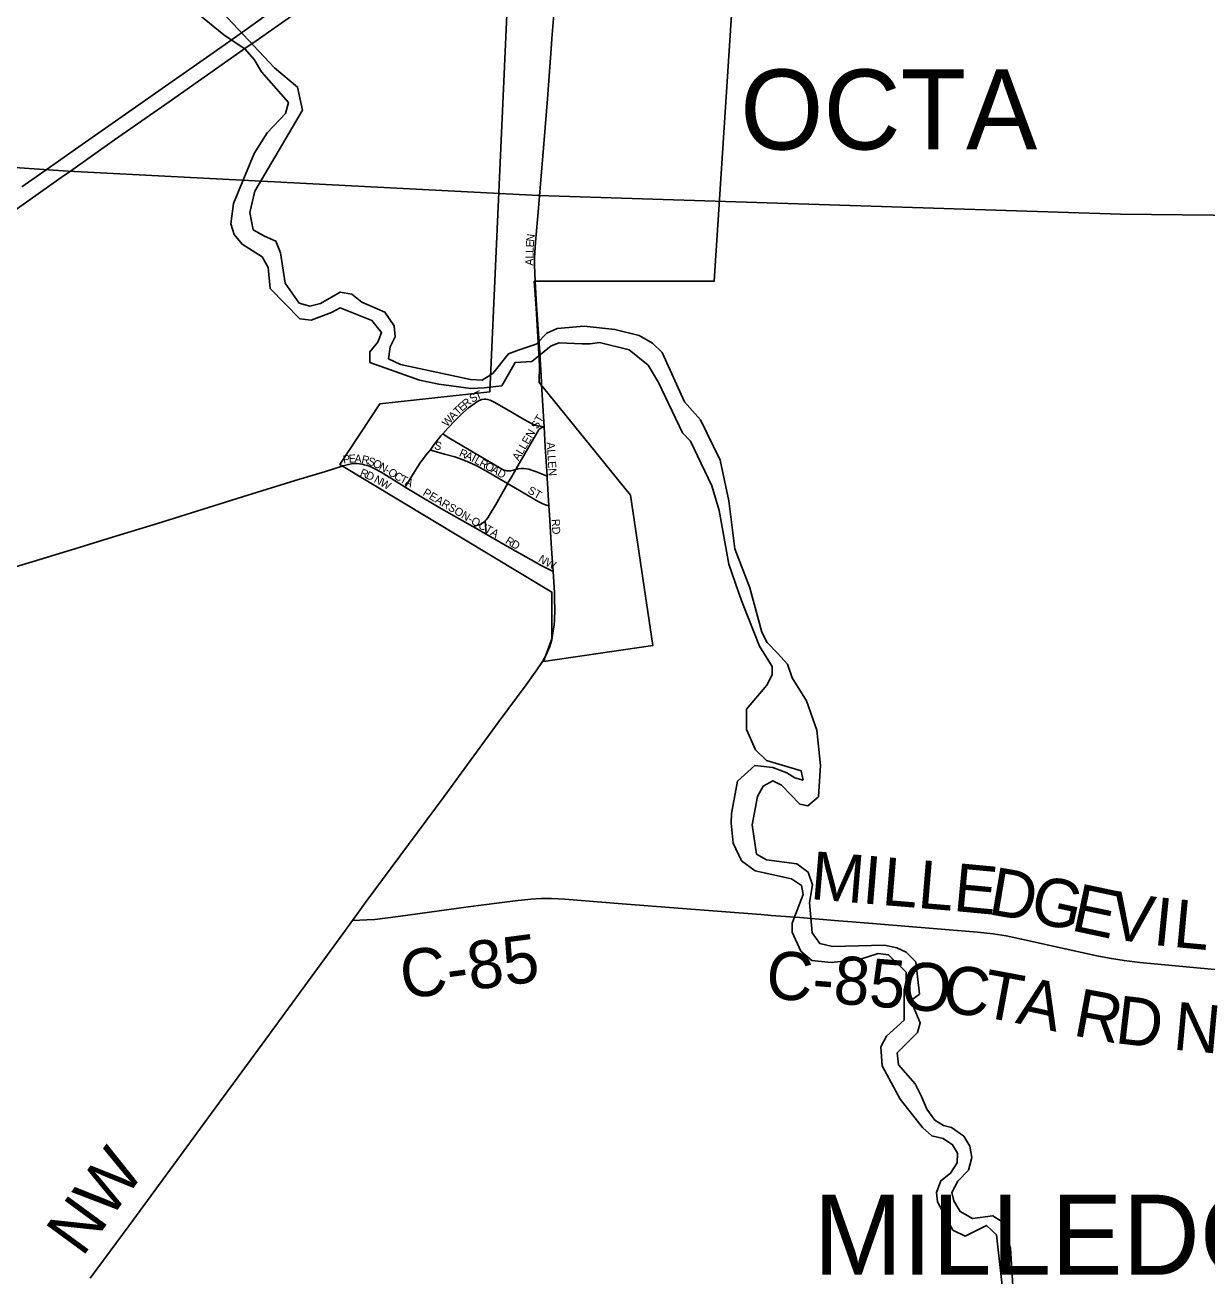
# Model space of a CAD drawing. Extents: x -49 to -8.2, y 9.4 to 23.5.
# Drawn here: x -41.383 to -40.683, y 16.498 to 17.238 of the extents above; entities that cross this region are included whole.
import ezdxf

# ---------------------------------------------------------------- set-up
doc = ezdxf.new("R2010")
doc.units = 0
for name, color, linetype in [('GM_X_City_Street', 7, 'Continuous'), ('GM_X_City_Street_Text', 7, 'Continuous'), ('GM_X_Corporation', 7, 'Continuous'), ('GM_X_Corporation_Text', 7, 'Continuous'), ('GM_X_County_Road', 7, 'Continuous'), ('GM_X_County_Road_Text', 7, 'Continuous'), ('GM_X_Interstate_Route', 7, 'Continuous'), ('GM_X_Major_River', 7, 'Continuous'), ('GM_X_Township', 7, 'Continuous')]:
    doc.layers.add(name, color=color, linetype=linetype)

msp = doc.modelspace()

# ---------------------------------------------------------------- linework, layer by layer
at = {"layer": 'GM_X_City_Street'}
for points in [[(-41.07819, 17.13694), (-41.07627, 17.16039), (-41.07346, 17.19439), (-41.07111, 17.22662), (-41.07087, 17.22997), (-41.06839, 17.26088)], [(-41.08079, 17.08632), (-41.08118, 17.09559), (-41.08113, 17.10021), (-41.08053, 17.10948), (-41.0788, 17.12956), (-41.07819, 17.13694)], [(-41.07555, 17.0002), (-41.07707, 17.02518)], [(-41.13552, 16.996), (-41.13246, 16.99939), (-41.12818, 17.00386), (-41.12367, 17.00837), (-41.12026, 17.01136), (-41.11782, 17.01327), (-41.11527, 17.01499), (-41.11392, 17.01574), (-41.11247, 17.01629), (-41.11094, 17.01655)], [(-41.11094, 17.01655), (-41.11003, 17.0166), (-41.10895, 17.01641), (-41.1075, 17.01594), (-41.10475, 17.01465), (-41.09681, 17.0101), (-41.08625, 17.0039), (-41.08221, 17.00177), (-41.08081, 17.00117), (-41.07935, 17.00073), (-41.07783, 17.00052), (-41.07555, 17.0002)], [(-41.09222, 16.97497), (-41.09021, 16.97839), (-41.07901, 16.99785), (-41.07858, 16.9986), (-41.07815, 16.99908), (-41.07736, 16.99959), (-41.07555, 17.0002)], [(-41.0737, 16.97089), (-41.07484, 16.98843), (-41.07555, 17.0002)], [(-41.14285, 16.98665), (-41.14078, 16.98951), (-41.1366, 16.99478), (-41.13552, 16.996)], [(-41.13552, 16.996), (-41.13538, 16.99591), (-41.13202, 16.99366), (-41.11322, 16.98258), (-41.10116, 16.97544), (-41.09975, 16.97476), (-41.09827, 16.97429), (-41.09756, 16.97413), (-41.09673, 16.97411), (-41.09597, 16.97417), (-41.09518, 16.97422), (-41.09366, 16.97457), (-41.09222, 16.97497)], [(-41.15781, 16.96456), (-41.15738, 16.96524), (-41.15374, 16.971), (-41.15075, 16.97611), (-41.14854, 16.97941), (-41.14699, 16.98147), (-41.14558, 16.98345), (-41.14285, 16.98665)], [(-41.14285, 16.98665), (-41.14205, 16.98623), (-41.13447, 16.9841), (-41.12844, 16.9824), (-41.12399, 16.98091), (-41.11965, 16.97916), (-41.11541, 16.97712), (-41.10855, 16.97336), (-41.10191, 16.96943), (-41.09714, 16.96666)], [(-41.19446, 16.97705), (-41.19131, 16.97787), (-41.18955, 16.97822), (-41.18793, 16.97842), (-41.18625, 16.9785), (-41.18475, 16.9783), (-41.18329, 16.97806), (-41.182, 16.97779), (-41.18033, 16.97734), (-41.17889, 16.97684), (-41.1761, 16.97561), (-41.17207, 16.97336), (-41.16153, 16.96681), (-41.15781, 16.96456)], [(-41.09222, 16.97497), (-41.09066, 16.97542), (-41.08912, 16.97558), (-41.08757, 16.97553), (-41.08602, 16.97535), (-41.08449, 16.97504), (-41.08299, 16.97463), (-41.08004, 16.97362), (-41.07717, 16.97239), (-41.0737, 16.97089)], [(-41.09714, 16.96666), (-41.09469, 16.97081), (-41.09222, 16.97497)], [(-41.07269, 16.95334), (-41.07363, 16.96986), (-41.0737, 16.97089)], [(-41.15781, 16.96456), (-41.14691, 16.95797), (-41.1362, 16.95169), (-41.11775, 16.94117)], [(-41.11038, 16.94454), (-41.10982, 16.94513), (-41.10888, 16.94634), (-41.10803, 16.94762), (-41.10414, 16.95431), (-41.09729, 16.96643), (-41.09714, 16.96666)], [(-41.09714, 16.96666), (-41.0925, 16.96395), (-41.07906, 16.95595), (-41.07627, 16.95456), (-41.07479, 16.95406), (-41.07269, 16.95334)], [(-41.07023, 16.9146), (-41.0711, 16.92807), (-41.07239, 16.94819), (-41.07269, 16.95334)], [(-41.11775, 16.94117), (-41.11737, 16.94127), (-41.11559, 16.9417), (-41.11347, 16.94235), (-41.11281, 16.94264), (-41.11211, 16.94309), (-41.11088, 16.94402), (-41.11038, 16.94454)], [(-41.11775, 16.94117), (-41.11597, 16.94015), (-41.10988, 16.93663)], [(-41.10988, 16.93663), (-41.10992, 16.93734), (-41.11005, 16.93929), (-41.11022, 16.94191), (-41.11036, 16.94419), (-41.11038, 16.94454)], [(-41.10988, 16.93663), (-41.09581, 16.9285), (-41.07683, 16.91787), (-41.07403, 16.91648), (-41.07023, 16.9146)], [(-41.06942, 16.90207), (-41.07023, 16.9146)]]:
    msp.add_lwpolyline(points, dxfattribs=at)
at = {"layer": 'GM_X_Corporation'}
msp.add_lwpolyline([(-40.96096, 17.29862), (-40.97477, 17.0863), (-41.08141, 17.08629), (-41.08018, 17.07045), (-41.07818, 17.03646), (-41.07853, 17.02636), (-41.02443, 16.9598), (-41.01126, 16.87068), (-41.07582, 16.86121), (-41.07096, 16.87465), (-41.071, 16.90237), (-41.19642, 16.97793), (-41.1728, 17.01378), (-41.10769, 17.02084), (-41.09569, 17.28796)], dxfattribs=at)
at = {"layer": 'GM_X_County_Road'}
for points in [[(-41.07707, 17.02518), (-41.07714, 17.02675), (-41.07813, 17.04401), (-41.07996, 17.07222), (-41.08079, 17.08632)], [(-41.52576, 16.81187), (-41.52231, 16.81517), (-41.50199, 16.83436), (-41.43997, 16.89308), (-41.43421, 16.89825), (-41.43062, 16.90117), (-41.42685, 16.90383), (-41.42421, 16.9054), (-41.42146, 16.90677), (-41.41718, 16.90852), (-41.40984, 16.91096), (-41.3786, 16.92032), (-41.35336, 16.92803), (-41.33107, 16.93481), (-41.30437, 16.94307), (-41.25398, 16.95879), (-41.22281, 16.96835), (-41.20499, 16.97382), (-41.19446, 16.97705)], [(-41.07655, 16.86137), (-41.07458, 16.86481), (-41.07222, 16.8702), (-41.071, 16.87416), (-41.07029, 16.87818), (-41.0696, 16.88278), (-41.06936, 16.88587), (-41.06921, 16.89204), (-41.06935, 16.8982), (-41.06942, 16.90207)], [(-41.18891, 16.70801), (-41.18081, 16.71931), (-41.16598, 16.73913), (-41.13472, 16.78145), (-41.12471, 16.79521), (-41.10269, 16.82511), (-41.08619, 16.84755), (-41.07992, 16.85641), (-41.07655, 16.86137)], [(-41.18891, 16.70801), (-41.18056, 16.7084), (-41.17581, 16.70865), (-41.16195, 16.71044), (-41.12043, 16.71604), (-41.09273, 16.71969), (-41.08348, 16.72074), (-41.07728, 16.72111), (-41.07108, 16.72109), (-41.06333, 16.72065), (-41.0293, 16.71787), (-40.9937, 16.71515), (-40.9705, 16.71328), (-40.94729, 16.71152), (-40.9412, 16.71105)], [(-40.9412, 16.71105), (-40.92408, 16.70972), (-40.90135, 16.70783)], [(-41.34422, 16.49631), (-41.32114, 16.52756), (-41.29085, 16.56893), (-41.27517, 16.59018), (-41.24022, 16.63778), (-41.19616, 16.69795), (-41.18891, 16.70801)], [(-40.90135, 16.70783), (-40.89314, 16.70715), (-40.84518, 16.70339), (-40.81889, 16.70112), (-40.80964, 16.70005), (-40.80197, 16.69886), (-40.79285, 16.69703), (-40.7671, 16.69124), (-40.74738, 16.68698), (-40.73976, 16.68553), (-40.73209, 16.68433), (-40.72285, 16.68319), (-40.6425, 16.6756), (-40.60388, 16.67186), (-40.5838, 16.66994), (-40.56835, 16.66846), (-40.54056, 16.66566), (-40.52357, 16.66402), (-40.50505, 16.66203), (-40.47726, 16.65919), (-40.47469, 16.65893)]]:
    msp.add_lwpolyline(points, dxfattribs=at)
at = {"layer": 'GM_X_Interstate_Route'}
for points in [[(-41.40109, 17.11979), (-41.36133, 17.14783), (-41.35591, 17.15146), (-41.32982, 17.16999), (-41.29744, 17.19253), (-41.25066, 17.22537), (-41.2479, 17.22731), (-41.23285, 17.23785), (-41.20004, 17.26087)], [(-41.38473, 17.14223), (-41.37032, 17.15236), (-41.35103, 17.16579), (-41.31929, 17.18793), (-41.26744, 17.22433), (-41.25415, 17.23378), (-41.23997, 17.24376)]]:
    msp.add_lwpolyline(points, dxfattribs=at)
at = {"layer": 'GM_X_Major_River'}
for points in [[(-41.28847, 17.25114), (-41.26505, 17.23207), (-41.25241, 17.22378), (-41.24719, 17.21761), (-41.24275, 17.21033), (-41.22688, 17.19222), (-41.2287, 17.18561), (-41.23953, 17.17421), (-41.24714, 17.162), (-41.2594, 17.1324), (-41.26093, 17.12027), (-41.25894, 17.11398), (-41.25428, 17.1082), (-41.24243, 17.10079), (-41.23892, 17.09447), (-41.2376, 17.08211), (-41.22021, 17.06416), (-41.21338, 17.06329), (-41.20133, 17.06784), (-41.19634, 17.0706), (-41.17746, 17.06307), (-41.17187, 17.05595), (-41.17386, 17.05029), (-41.17871, 17.04449), (-41.17862, 17.03822), (-41.14932, 17.02786), (-41.13777, 17.02539), (-41.11899, 17.0228), (-41.11104, 17.02321), (-41.10057, 17.02437), (-41.0927, 17.0383), (-41.08281, 17.0389), (-41.07144, 17.0482), (-41.06666, 17.04983), (-41.05299, 17.04922), (-41.04823, 17.04933), (-41.04271, 17.05), (-41.0251, 17.04572), (-41.01403, 17.03661), (-41.00774, 17.02644), (-40.99358, 16.99659), (-40.98891, 16.99177), (-40.97622, 16.96536), (-40.97189, 16.95067), (-40.96613, 16.91888), (-40.96051, 16.90227), (-40.95814, 16.89577), (-40.9481, 16.87036), (-40.9405, 16.85827), (-40.94058, 16.85334), (-40.94372, 16.84732), (-40.95574, 16.83309), (-40.95574, 16.82113), (-40.95042, 16.80908), (-40.94387, 16.80271), (-40.92344, 16.79667), (-40.9222, 16.79115)], [(-40.9194, 16.77591), (-40.91304, 16.78131), (-40.91199, 16.79971), (-40.91412, 16.82063), (-40.92011, 16.838), (-40.92864, 16.85162), (-40.93155, 16.85964), (-40.93733, 16.86619), (-40.9435, 16.87256), (-40.94664, 16.87869), (-40.95381, 16.905), (-40.96257, 16.92793), (-40.9661, 16.95646), (-40.97141, 16.98047), (-40.983, 17.00439), (-40.99252, 17.01499), (-41.00574, 17.04425), (-41.01135, 17.04966), (-41.01926, 17.05416), (-41.03365, 17.05782), (-41.05187, 17.05983), (-41.06786, 17.05839), (-41.07398, 17.05565), (-41.08017, 17.04911), (-41.0903, 17.04567), (-41.09661, 17.04331), (-41.10592, 17.03169), (-41.11226, 17.02781), (-41.1191, 17.02812), (-41.16058, 17.03716), (-41.16756, 17.0405), (-41.16669, 17.04751), (-41.16374, 17.05354), (-41.1642, 17.06), (-41.16977, 17.06807), (-41.18336, 17.07399), (-41.18937, 17.07865), (-41.19619, 17.0799), (-41.2079, 17.07326), (-41.2142, 17.07166), (-41.22044, 17.07328), (-41.2288, 17.08519), (-41.23156, 17.10308), (-41.23429, 17.11015), (-41.24109, 17.11311), (-41.24768, 17.11683), (-41.2498, 17.12711), (-41.24674, 17.13959), (-41.2186, 17.18752), (-41.22142, 17.20124), (-41.23511, 17.21267), (-41.26594, 17.24545)], [(-40.9222, 16.79115), (-40.92712, 16.79237), (-40.93192, 16.79548), (-40.94016, 16.79849), (-40.95076, 16.79979), (-40.96099, 16.79047), (-40.96453, 16.77135), (-40.96481, 16.76566), (-40.96367, 16.75388), (-40.95871, 16.74335), (-40.95063, 16.73752), (-40.92904, 16.7326), (-40.92321, 16.72871), (-40.92215, 16.72338), (-40.9287, 16.7064), (-40.92879, 16.70109), (-40.92365, 16.6898), (-40.91708, 16.68438), (-40.90569, 16.68324), (-40.88875, 16.68504), (-40.87786, 16.68847), (-40.8716, 16.68779), (-40.86112, 16.67737), (-40.8612, 16.67243), (-40.86243, 16.66695), (-40.86234, 16.6491), (-40.87276, 16.6396), (-40.87628, 16.6332), (-40.87532, 16.62198), (-40.86481, 16.60226), (-40.85158, 16.58552), (-40.84596, 16.58068), (-40.83933, 16.57905), (-40.83369, 16.57535), (-40.83073, 16.57036), (-40.83101, 16.56467), (-40.83491, 16.55847), (-40.84068, 16.55401), (-40.84327, 16.54703), (-40.8426, 16.54152), (-40.83355, 16.52485), (-40.8262, 16.52131), (-40.81374, 16.52756), (-40.80775, 16.52195), (-40.80427, 16.49019)], [(-40.79783, 16.48838), (-40.79951, 16.51403), (-40.80496, 16.53007), (-40.80985, 16.53319), (-40.82185, 16.53168), (-40.82919, 16.53579), (-40.83308, 16.54212), (-40.83414, 16.54707), (-40.83061, 16.55385), (-40.82424, 16.56019), (-40.8224, 16.56776), (-40.82344, 16.57442), (-40.82714, 16.58036), (-40.83447, 16.58561), (-40.83921, 16.58664), (-40.84428, 16.58995), (-40.84894, 16.5963), (-40.85204, 16.60394), (-40.85591, 16.61141), (-40.86581, 16.62259), (-40.86645, 16.62981), (-40.85447, 16.64176), (-40.85286, 16.64743), (-40.85854, 16.66062), (-40.85334, 16.66452), (-40.85551, 16.68354), (-40.86112, 16.68933), (-40.86678, 16.69189), (-40.87398, 16.69334), (-40.90478, 16.69271), (-40.91236, 16.69436), (-40.91682, 16.7007), (-40.91843, 16.71876), (-40.91674, 16.72917), (-40.91928, 16.73662), (-40.92585, 16.74166), (-40.94387, 16.74386), (-40.9499, 16.74738), (-40.95228, 16.76469), (-40.94916, 16.78135), (-40.94583, 16.78756), (-40.94007, 16.79069), (-40.93498, 16.78813), (-40.92414, 16.77694), (-40.9194, 16.77591)]]:
    msp.add_lwpolyline(points, dxfattribs=at)
at = {"layer": 'GM_X_Township'}
msp.add_lwpolyline([(-40.58818, 17.12439), (-40.73433, 17.12609), (-41.0788, 17.13706), (-41.35732, 17.15149), (-41.42352, 17.15606), (-41.91904, 17.28606), (-42.42346, 17.41553), (-42.43066, 17.336), (-42.47792, 16.8137), (-42.4838, 16.7488), (-42.51639, 16.39726), (-42.54815, 16.03753), (-42.58215, 15.66156), (-42.60629, 15.39444), (-42.63454, 15.08208), (-42.5793, 15.07686), (-42.34431, 15.05466), (-41.42871, 14.96816), (-41.35642, 14.96138), (-41.04989, 14.93259), (-40.85025, 14.91381), (-40.65011, 14.89497)], dxfattribs=at)

# ---------------------------------------------------------------- texts
at = {"layer": 'GM_X_City_Street_Text'}
for s, height, rotation, p in [('E', 0.00473, 87.13077, (-41.08166, 17.10631)), ('N', 0.00473, 82.56858, (-41.08151, 17.10954)), ('L', 0.00473, 88.23452, (-41.08187, 17.09967)), ('L', 0.00473, 88.25105, (-41.08177, 17.10301)), ('A', 0.00473, 88.25105, (-41.08199, 17.09551)), ('S', 0.00473, 32.47747, (-41.11796, 17.01429)), ('T', 0.00473, 23.91255, (-41.11531, 17.01599)), ('T', 0.00473, 44.15009, (-41.12652, 17.00676)), ('E', 0.00473, 41.28871, (-41.12417, 17.00904)), ('R', 0.00473, 40.01389, (-41.12169, 17.01122)), ('W', 0.00473, 47.48542, (-41.13303, 16.99983)), ('A', 0.00473, 45.81912, (-41.1294, 17.0038)), ('ALLEN ST', 0.004735, 59.49183, (-41.09064, 16.97969)), ('S', 0.00473, 345.97019, (-41.1409, 16.98719)), ('ALLEN', 0.004735, 273.72955, (-41.074, 16.99096)), ('P', 0.00473, 8.64021, (-41.19423, 16.97844)), ('E', 0.00473, 3.14346, (-41.19106, 16.97893)), ('A', 0.00473, 356.61044, (-41.18787, 16.97911)), ('R', 0.00473, 347.09456, (-41.18392, 16.9789)), ('R', 0.00473, 337.49968, (-41.1262, 16.98298)), ('A', 0.00473, 336.45699, (-41.12276, 16.98155)), ('I', 0.00473, 332.80944, (-41.11901, 16.97992)), ('L', 0.00473, 331.14971, (-41.11719, 16.97899)), ('R', 0.00473, 338.30683, (-41.18491, 16.97129)), ('S', 0.00473, 339.8372, (-41.18041, 16.9781)), ('O', 0.00473, 334.90125, (-41.17738, 16.977)), ('N', 0.00473, 330.55059, (-41.17369, 16.97527)), ('R', 0.00473, 331.04449, (-41.11427, 16.97738)), ('O', 0.00473, 331.02806, (-41.11099, 16.97557)), ('A', 0.00473, 331.04321, (-41.10735, 16.97354)), ('D', 0.00473, 335.19434, (-41.18149, 16.96993)), ('N', 0.00473, 331.3721, (-41.17665, 16.96767)), ('W', 0.00473, 330.1175, (-41.17302, 16.96569)), ('-', 0.00473, 327.97145, (-41.17011, 16.97325)), ('O', 0.00473, 327.54055, (-41.16836, 16.97215)), ('C', 0.00473, 328.08479, (-41.1648, 16.96989)), ('T', 0.00473, 331.81755, (-41.16132, 16.96774)), ('A', 0.00473, 333.36945, (-41.15826, 16.9661)), ('D', 0.00473, 331.04321, (-41.1037, 16.97153)), ('PEARSON-OCTA', 0.0047348, 329.48118, (-41.14771, 16.95998)), ('ST', 0.004735, 330.2568, (-41.08568, 16.96126)), ('RD', 0.004735, 273.01099, (-41.07108, 16.94553)), ('R', 0.00473, 327.05758, (-41.09895, 16.93164)), ('D', 0.00473, 330.76198, (-41.09552, 16.92943)), ('N', 0.00473, 327.55899, (-41.07939, 16.92082)), ('W', 0.00473, 335.89516, (-41.07522, 16.91823))]:
    msp.add_text(s, height=height, rotation=rotation, dxfattribs=at).set_placement(p)
at = {"layer": 'GM_X_Corporation_Text'}
for s, height, p in [('OCTA', 0.047348, (-40.95945, 17.16432)), ('MILLEDGEVILLE', 0.0473485, (-40.91612, 16.49841))]:
    msp.add_text(s, height=height, rotation=0.00001, dxfattribs=at).set_placement(p)
at = {"layer": 'GM_X_County_Road_Text'}
for s, height, rotation, p in [('M', 0.02841, 355.25402, (-40.91853, 16.72079)), ('I', 0.02841, 355.25817, (-40.8878, 16.71824)), ('L', 0.02841, 355.25486, (-40.87617, 16.71728)), ('L', 0.02841, 355.23743, (-40.855, 16.71552)), ('E', 0.02841, 354.63524, (-40.8339, 16.71376)), ('D', 0.02841, 350.27058, (-40.81331, 16.71185)), ('G', 0.02841, 347.75488, (-40.789, 16.70769)), ('E', 0.02841, 348.01862, (-40.76442, 16.70236)), ('V', 0.02841, 351.32401, (-40.74188, 16.69762)), ('I', 0.02841, 354.25438, (-40.71559, 16.69365)), ('L', 0.02841, 354.6543, (-40.70376, 16.69246)), ('C-85', 0.028409, 7.50904, (-41.15884, 16.6615)), ('C-85', 0.028409, 355.54947, (-40.94484, 16.66214)), ('O', 0.02841, 354.84218, (-40.86513, 16.65591)), ('C', 0.02841, 354.09212, (-40.84033, 16.65367)), ('T', 0.02841, 349.48012, (-40.81772, 16.65136)), ('A', 0.02841, 347.64623, (-40.79706, 16.64753)), ('R', 0.02841, 349.48992, (-40.76311, 16.64013)), ('D', 0.02841, 353.2407, (-40.73816, 16.63557)), ('N', 0.02841, 354.71575, (-40.70383, 16.63171)), ('NW', 0.028409, 53.79018, (-41.34888, 16.50834))]:
    msp.add_text(s, height=height, rotation=rotation, dxfattribs=at).set_placement(p)

doc.saveas('drawing.dxf')
